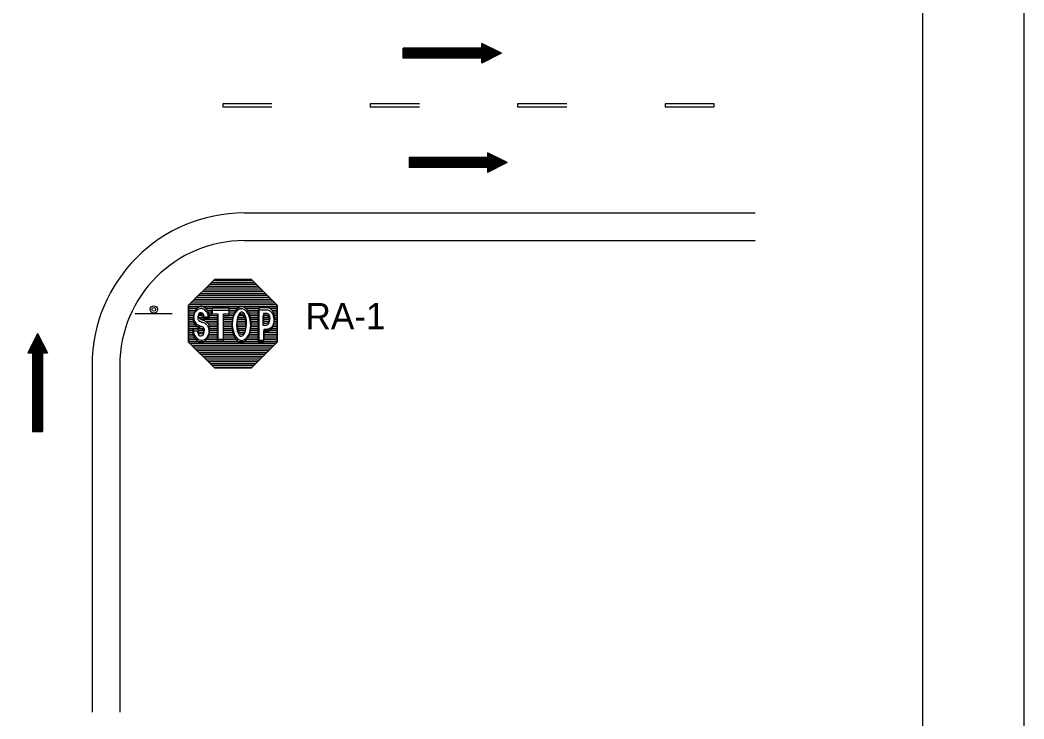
# Model space of a CAD drawing. Extents: x 2111 to 2327, y 208 to 487.
# Drawn here: x 2228.5 to 2327.3, y 280.7 to 349.6 of the extents above; entities that cross this region are included whole.
import ezdxf

# ---------------------------------------------------------------- set-up
doc = ezdxf.new("R2010")
doc.units = 0
for name, color, linetype in [('Level 10', 7, 'Continuous'), ('Level 2', 7, 'Continuous'), ('Level 44', 7, 'Continuous'), ('Level 60', 7, 'Continuous')]:
    doc.layers.add(name, color=color, linetype=linetype)

msp = doc.modelspace()

# ---------------------------------------------------------------- linework, layer by layer
at = {"layer": 'Level 10'}
for p, q in [((2275.874, 346.307), (2273.937, 347.276)), ((2273.937, 346.791), (2273.937, 347.276)), ((2274.181, 347.153), (2273.937, 347.153)), ((2274.422, 347.032), (2273.937, 347.032)), ((2273.937, 346.791), (2266.196, 346.791)), ((2266.196, 345.824), (2266.196, 346.791)), ((2274.906, 346.791), (2266.196, 346.791)), ((2275.148, 346.67), (2266.196, 346.67)), ((2275.389, 346.549), (2266.196, 346.549)), ((2275.631, 346.428), (2266.196, 346.428)), ((2275.874, 346.307), (2266.196, 346.307)), ((2275.631, 346.186), (2266.196, 346.186)), ((2275.389, 346.065), (2266.196, 346.065)), ((2274.664, 346.913), (2273.937, 346.913)), ((2275.874, 346.307), (2273.937, 345.338)), ((2275.148, 345.944), (2266.196, 345.944)), ((2273.937, 345.824), (2266.196, 345.824)), ((2274.906, 345.824), (2266.196, 345.824)), ((2273.937, 345.338), (2273.937, 345.824)), ((2274.664, 345.703), (2273.937, 345.703)), ((2274.422, 345.582), (2273.937, 345.582)), ((2274.181, 345.461), (2273.937, 345.461)), ((2276.452, 335.537), (2274.516, 336.504)), ((2274.516, 336.504), (2274.516, 336.021)), ((2274.758, 336.384), (2274.516, 336.384)), ((2275, 336.263), (2274.516, 336.263)), ((2275.242, 336.142), (2274.516, 336.142)), ((2274.516, 336.021), (2266.774, 336.021)), ((2266.774, 336.021), (2266.774, 335.052)), ((2275.484, 336.021), (2266.774, 336.021)), ((2275.725, 335.9), (2266.774, 335.9)), ((2275.967, 335.779), (2266.774, 335.779)), ((2276.209, 335.658), (2266.774, 335.658)), ((2276.452, 335.537), (2266.774, 335.537)), ((2276.209, 335.416), (2266.774, 335.416)), ((2275.967, 335.296), (2266.774, 335.296)), ((2275.725, 335.173), (2266.774, 335.173)), ((2276.452, 335.537), (2274.516, 334.569)), ((2274.516, 335.052), (2266.774, 335.052)), ((2275.484, 335.052), (2266.774, 335.052)), ((2274.516, 335.052), (2274.516, 334.569)), ((2275.242, 334.933), (2274.516, 334.933)), ((2275, 334.81), (2274.516, 334.81)), ((2274.758, 334.69), (2274.516, 334.69)), ((2250.564, 330.571), (2300.839, 330.571)), ((2250.564, 327.844), (2300.839, 327.844)), ((2230.192, 318.708), (2229.225, 316.772)), ((2230.071, 318.465), (2230.071, 309.03)), ((2230.192, 318.708), (2230.192, 309.03)), ((2230.192, 318.708), (2231.16, 316.772)), ((2230.313, 318.465), (2230.313, 309.03)), ((2229.587, 317.498), (2229.587, 316.772)), ((2229.708, 317.74), (2229.708, 309.03)), ((2229.829, 317.981), (2229.829, 309.03)), ((2229.95, 318.223), (2229.95, 309.03)), ((2230.433, 318.223), (2230.433, 309.03)), ((2230.556, 317.981), (2230.556, 309.03)), ((2230.677, 317.74), (2230.677, 309.03)), ((2230.796, 317.498), (2230.796, 316.772)), ((2229.225, 316.772), (2229.708, 316.772)), ((2229.345, 317.014), (2229.345, 316.772)), ((2229.466, 317.256), (2229.466, 316.772)), ((2229.708, 316.772), (2229.708, 309.03)), ((2230.677, 316.772), (2230.677, 309.03)), ((2230.677, 316.772), (2231.16, 316.772)), ((2230.919, 317.256), (2230.919, 316.772)), ((2231.039, 317.014), (2231.039, 316.772)), ((2235.564, 315.571), (2235.564, 281.396)), ((2238.291, 315.571), (2238.291, 281.396)), ((2229.708, 309.03), (2230.677, 309.03))]:
    msp.add_line(p, q, dxfattribs=at)
for radius in [15, 12.273]:
    msp.add_arc((2250.564, 315.571), radius, 90, 180, dxfattribs=at)
at = {"layer": 'Level 2'}
for p, q in [((2253.279, 341.303), (2248.441, 341.303)), ((2248.441, 341.303), (2248.441, 341.013)), ((2248.441, 341.013), (2253.279, 341.013)), ((2267.793, 341.303), (2262.955, 341.303)), ((2262.955, 341.303), (2262.955, 341.013)), ((2262.955, 341.013), (2267.793, 341.013)), ((2282.307, 341.303), (2277.469, 341.303)), ((2277.469, 341.303), (2277.469, 341.013)), ((2277.469, 341.013), (2282.307, 341.013)), ((2296.821, 341.303), (2291.983, 341.303)), ((2291.983, 341.303), (2291.983, 341.013)), ((2291.983, 341.013), (2296.821, 341.013)), ((2296.821, 341.013), (2296.821, 341.303))]:
    msp.add_line(p, q, dxfattribs=at)
at = {"layer": 'Level 44'}
for p, q in [((2247.623, 324.02), (2245.075, 321.474)), ((2251.252, 324.02), (2247.623, 324.02)), ((2253.8, 321.474), (2251.252, 324.02)), ((2245.075, 321.474), (2245.075, 317.844)), ((2253.8, 317.844), (2253.8, 321.474)), ((2239.822, 320.657), (2243.451, 320.657)), ((2247.114, 320.305), (2246.57, 320.305)), ((2247.33, 320.428), (2247.33, 320.987)), ((2247.33, 320.987), (2249.031, 320.987)), ((2247.919, 320.428), (2247.33, 320.428)), ((2247.377, 321.198), (2247.377, 320.639)), ((2249.074, 321.198), (2247.377, 321.198)), ((2247.377, 320.639), (2247.963, 320.639)), ((2247.919, 317.916), (2247.919, 320.428)), ((2247.963, 320.639), (2247.963, 318.126)), ((2249.031, 320.414), (2248.471, 320.414)), ((2248.471, 320.414), (2248.471, 317.916)), ((2248.516, 318.126), (2248.516, 320.624)), ((2248.516, 320.624), (2249.074, 320.624)), ((2249.031, 320.987), (2249.031, 320.414)), ((2249.074, 320.624), (2249.074, 321.198)), ((2250.206, 320.584), (2250.229, 320.589)), ((2250.228, 321.128), (2250.244, 321.129)), ((2251.926, 317.823), (2251.926, 321.015)), ((2251.926, 321.015), (2252.82, 321.015)), ((2252.863, 321.227), (2251.971, 321.227)), ((2251.971, 321.227), (2251.971, 318.033)), ((2252.391, 320.443), (2252.391, 319.514)), ((2252.738, 320.443), (2252.391, 320.443)), ((2252.738, 320.443), (2252.391, 320.443)), ((2252.391, 320.443), (2252.391, 319.514)), ((2252.783, 320.653), (2252.435, 320.653)), ((2252.435, 320.653), (2252.435, 319.724)), ((2252.435, 320.653), (2252.435, 319.724)), ((2252.783, 320.653), (2252.435, 320.653)), ((2247.07, 320.094), (2246.525, 320.094)), ((2252.391, 319.514), (2252.731, 319.514)), ((2252.391, 319.514), (2252.731, 319.514)), ((2252.435, 319.724), (2252.777, 319.724)), ((2252.435, 319.724), (2252.777, 319.724)), ((2245.452, 318.948), (2245.952, 318.948)), ((2245.495, 319.158), (2245.998, 319.158)), ((2245.61, 318.315), (2245.608, 318.318)), ((2252.773, 318.919), (2252.456, 318.91)), ((2252.456, 318.91), (2252.79, 318.91)), ((2252.456, 318.91), (2252.456, 317.823)), ((2252.501, 318.033), (2252.501, 319.121)), ((2252.501, 319.121), (2252.835, 319.121)), ((2245.075, 317.844), (2247.623, 315.296)), ((2248.471, 317.916), (2247.919, 317.916)), ((2247.963, 318.126), (2248.516, 318.126)), ((2251.252, 315.296), (2253.8, 317.844)), ((2252.456, 317.823), (2251.926, 317.823)), ((2251.971, 318.033), (2252.501, 318.033)), ((2247.623, 315.296), (2251.252, 315.296))]:
    msp.add_line(p, q, dxfattribs=at)
msp.add_lwpolyline([(2253.801, 317.844), (2251.252, 315.296), (2247.623, 315.296), (2245.075, 317.844), (2245.075, 321.474), (2247.623, 324.022), (2251.252, 324.022), (2253.801, 321.474)], close=True, dxfattribs=at)
for points in [[(2246.963, 323.359), (2251.913, 323.359)], [(2247.143, 323.542), (2251.732, 323.542)], [(2247.325, 323.724), (2251.543, 323.724)], [(2247.508, 323.904), (2251.368, 323.904)], [(2245.873, 322.272), (2253.002, 322.272)], [(2246.055, 322.453), (2252.82, 322.453)], [(2246.237, 322.634), (2252.638, 322.634)], [(2246.418, 322.817), (2252.457, 322.817)], [(2246.599, 322.998), (2252.275, 322.998)], [(2246.78, 323.179), (2252.087, 323.179)], [(2245.075, 321.364), (2253.8, 321.364)], [(2245.148, 321.545), (2253.727, 321.545)], [(2245.328, 321.728), (2253.546, 321.728)], [(2245.51, 321.909), (2253.365, 321.909)], [(2245.693, 322.089), (2253.183, 322.089)], [(2245.075, 321.183), (2245.917, 321.183)], [(2245.075, 321.002), (2245.764, 321.002)], [(2245.075, 320.819), (2245.663, 320.819)], [(2245.075, 320.639), (2245.613, 320.639)], [(2245.075, 320.458), (2245.577, 320.458)], [(2245.075, 320.275), (2245.568, 320.275)], [(2246.012, 320.458), (2246.578, 320.458)], [(2246.04, 320.275), (2247.963, 320.275)], [(2246.092, 320.639), (2246.498, 320.639)], [(2246.753, 321.183), (2247.377, 321.183)], [(2246.912, 321.002), (2247.377, 321.002)], [(2247.013, 320.819), (2247.377, 320.819)], [(2247.064, 320.639), (2247.377, 320.639)], [(2247.108, 320.458), (2247.963, 320.458)], [(2248.516, 320.458), (2249.482, 320.458)], [(2248.516, 320.275), (2249.437, 320.275)], [(2249.074, 321.183), (2249.917, 321.183)], [(2249.074, 321.002), (2249.749, 321.002)], [(2249.074, 320.819), (2249.627, 320.819)], [(2249.074, 320.639), (2249.546, 320.639)], [(2249.903, 320.275), (2250.693, 320.275)], [(2249.953, 320.458), (2250.634, 320.458)], [(2250.039, 320.639), (2250.548, 320.639)], [(2250.686, 321.183), (2251.971, 321.183)], [(2250.861, 321.002), (2251.971, 321.002)], [(2250.977, 320.819), (2251.971, 320.819)], [(2251.056, 320.639), (2251.971, 320.639)], [(2251.122, 320.458), (2251.971, 320.458)], [(2251.164, 320.275), (2251.971, 320.275)], [(2252.435, 320.639), (2252.856, 320.639)], [(2252.435, 320.458), (2253.03, 320.458)], [(2252.435, 320.275), (2253.073, 320.275)], [(2253.03, 321.183), (2253.8, 321.183)], [(2253.263, 321.002), (2253.8, 321.002)], [(2253.378, 320.819), (2253.8, 320.819)], [(2253.466, 320.639), (2253.8, 320.639)], [(2253.508, 320.458), (2253.8, 320.458)], [(2253.532, 320.275), (2253.8, 320.275)], [(2245.075, 320.094), (2245.592, 320.094)], [(2245.075, 319.913), (2245.642, 319.913)], [(2245.075, 319.73), (2245.758, 319.73)], [(2245.075, 319.55), (2245.989, 319.55)], [(2245.075, 319.369), (2246.418, 319.369)], [(2246.273, 320.094), (2247.963, 320.094)], [(2246.679, 319.913), (2247.963, 319.913)], [(2246.927, 319.73), (2247.963, 319.73)], [(2247.064, 319.55), (2247.963, 319.55)], [(2247.114, 319.369), (2247.963, 319.369)], [(2248.516, 320.094), (2249.408, 320.094)], [(2248.516, 319.73), (2249.379, 319.73)], [(2248.516, 319.55), (2249.379, 319.55)], [(2248.516, 319.369), (2249.393, 319.369)], [(2248.523, 319.913), (2249.387, 319.913)], [(2249.829, 319.73), (2250.767, 319.73)], [(2249.829, 319.55), (2250.773, 319.55)], [(2249.843, 319.913), (2250.767, 319.913)], [(2249.852, 320.094), (2250.737, 320.094)], [(2249.852, 319.369), (2250.752, 319.369)], [(2251.201, 320.094), (2251.971, 320.094)], [(2251.208, 319.369), (2251.971, 319.369)], [(2251.216, 319.913), (2251.971, 319.913)], [(2251.223, 319.55), (2251.971, 319.55)], [(2251.231, 319.73), (2251.971, 319.73)], [(2252.428, 320.094), (2253.081, 320.094)], [(2252.435, 319.913), (2253.023, 319.913)], [(2253.278, 319.369), (2253.8, 319.369)], [(2253.401, 319.55), (2253.8, 319.55)], [(2253.466, 319.73), (2253.8, 319.73)], [(2253.517, 319.913), (2253.8, 319.913)], [(2253.538, 320.094), (2253.8, 320.094)], [(2245.075, 319.188), (2246.607, 319.188)], [(2245.075, 319.005), (2245.518, 319.005)], [(2245.075, 318.824), (2245.554, 318.824)], [(2245.075, 318.643), (2245.613, 318.643)], [(2245.075, 318.46), (2245.698, 318.46)], [(2245.075, 318.28), (2245.844, 318.28)], [(2246.012, 319.005), (2246.628, 319.005)], [(2246.07, 318.824), (2246.585, 318.824)], [(2246.853, 318.28), (2247.963, 318.28)], [(2246.983, 318.46), (2247.963, 318.46)], [(2247.072, 318.643), (2247.963, 318.643)], [(2247.129, 318.824), (2247.963, 318.824)], [(2247.143, 319.188), (2247.963, 319.188)], [(2247.143, 319.005), (2247.963, 319.005)], [(2248.516, 319.188), (2249.416, 319.188)], [(2248.516, 319.005), (2249.444, 319.005)], [(2248.516, 318.824), (2249.496, 318.824)], [(2248.516, 318.643), (2249.561, 318.643)], [(2248.516, 318.46), (2249.654, 318.46)], [(2248.516, 318.28), (2249.786, 318.28)], [(2249.888, 319.188), (2250.716, 319.188)], [(2249.946, 319.005), (2250.664, 319.005)], [(2250.024, 318.824), (2250.569, 318.824)], [(2250.794, 318.28), (2251.971, 318.28)], [(2250.926, 318.46), (2251.971, 318.46)], [(2251.019, 318.643), (2251.971, 318.643)], [(2251.092, 318.824), (2251.971, 318.824)], [(2251.143, 319.005), (2251.971, 319.005)], [(2251.179, 319.188), (2251.971, 319.188)], [(2252.501, 319.005), (2253.8, 319.005)], [(2252.501, 318.824), (2253.8, 318.824)], [(2252.501, 318.643), (2253.8, 318.643)], [(2252.501, 318.46), (2253.8, 318.46)], [(2252.501, 318.28), (2253.8, 318.28)], [(2253.03, 319.188), (2253.8, 319.188)], [(2245.075, 318.099), (2246.055, 318.099)], [(2245.075, 317.916), (2253.8, 317.916)], [(2245.184, 317.735), (2253.691, 317.735)], [(2245.365, 317.554), (2253.508, 317.554)], [(2245.547, 317.373), (2253.328, 317.373)], [(2246.613, 318.099), (2250.003, 318.099)], [(2250.577, 318.099), (2251.971, 318.099)], [(2252.501, 318.099), (2253.8, 318.099)], [(2245.728, 317.19), (2253.147, 317.19)], [(2245.91, 317.009), (2252.965, 317.009)], [(2246.092, 316.829), (2252.783, 316.829)], [(2246.273, 316.646), (2252.602, 316.646)], [(2246.453, 316.465), (2252.421, 316.465)], [(2246.635, 316.284), (2252.238, 316.284)], [(2246.818, 316.101), (2252.058, 316.101)], [(2246.998, 315.921), (2251.877, 315.921)], [(2247.18, 315.739), (2251.695, 315.739)], [(2247.368, 315.559), (2251.513, 315.559)], [(2247.543, 315.376), (2251.332, 315.376)]]:
    msp.add_lwpolyline(points, dxfattribs=at)
for radius in [0.363, 0.181]:
    msp.add_circle((2241.644, 321.064), radius, dxfattribs=at)
for centre, radius, start, end in [((2246.553, 320.459), 0.967, 123.3662, 155.67344), ((2246.331, 320.762), 0.591, 46.13686, 121.39871), ((2246.88, 320.131), 1.355, 157.73321, 177.13918), ((2246.757, 320.304), 1.19, 174.81715, 195.91834), ((2246.925, 320.342), 1.355, 157.73321, 177.13918), ((2246.509, 320.248), 0.967, 123.3662, 155.67344), ((2246.224, 320.197), 0.268, 164.13099, 238.14757), ((2246.259, 320.239), 0.294, 113.8064, 172.24074), ((2246.287, 320.552), 0.591, 46.13686, 121.39871), ((2246.269, 320.407), 0.268, 164.13099, 238.14757), ((2246.304, 320.45), 0.294, 113.8064, 172.24074), ((2246.236, 320.215), 0.308, 47.30173, 109.01194), ((2246.28, 320.426), 0.308, 47.30173, 109.01194), ((2246.092, 320.161), 0.45, 350.44122, 39.32441), ((2246.136, 320.372), 0.45, 350.44122, 39.32441), ((2246.04, 320.227), 0.998, 14.56402, 49.00631), ((2246.085, 320.438), 0.998, 14.56402, 49.00631), ((2245.686, 320.07), 1.381, 0.69518, 17.14515), ((2245.731, 320.281), 1.381, 0.69518, 17.14515), ((2252.685, 320.141), 0.315, 35.11978, 79.31166), ((2252.685, 320.141), 0.315, 35.11978, 79.31166), ((2252.73, 320.352), 0.315, 35.11978, 79.31166), ((2252.73, 320.352), 0.315, 35.11978, 79.31166), ((2252.771, 320.491), 0.53, 44.85284, 85.0441), ((2252.816, 320.701), 0.53, 44.85284, 85.0441), ((2252.538, 320.047), 0.489, 8.60306, 34.21696), ((2252.538, 320.047), 0.489, 8.60306, 34.21696), ((2252.583, 320.258), 0.489, 8.60306, 34.21696), ((2252.583, 320.258), 0.489, 8.60306, 34.21696), ((2252.565, 320.194), 0.52, 350.34165, 15.23421), ((2252.565, 320.194), 0.52, 350.34165, 15.23421), ((2252.605, 320.258), 0.814, 29.22414, 48.53082), ((2252.605, 320.258), 0.814, 29.22414, 48.53082), ((2252.65, 320.468), 0.814, 29.22414, 48.53082), ((2252.65, 320.468), 0.814, 29.22414, 48.53082), ((2252.594, 320.179), 0.864, 13.06738, 33.76202), ((2252.639, 320.389), 0.864, 13.06738, 33.76202), ((2251.818, 319.923), 1.68, 3.39027, 15.65974), ((2251.863, 320.134), 1.68, 3.39027, 15.65974), ((2246.713, 320.093), 1.19, 174.81715, 195.91834), ((2246.363, 320.058), 0.847, 200.4481, 235.11069), ((2246.408, 320.269), 0.847, 200.4481, 235.11069), ((2248.532, 324.894), 6.135, 244.46241, 248.83121), ((2248.577, 325.105), 6.135, 244.46241, 248.83121), ((2247.072, 321.551), 1.866, 237.98164, 250.97904), ((2247.117, 321.762), 1.866, 237.98164, 250.97904), ((2246.261, 319.01), 0.387, 34.20826, 74.15525), ((2245.976, 318.576), 1.305, 46.24648, 67.92633), ((2246.021, 318.786), 1.305, 46.24648, 67.92633), ((2248.645, 320.964), 2.281, 219.47897, 223.42605), ((2248.689, 321.174), 2.281, 219.47897, 223.42605), ((2245.74, 318.868), 1.359, 5.90969, 21.9865), ((2245.785, 319.078), 1.359, 5.90969, 21.9865), ((2252.658, 319.867), 0.361, 281.91914, 325.7868), ((2252.658, 319.867), 0.361, 281.91914, 325.7868), ((2252.703, 320.078), 0.361, 281.91914, 325.7868), ((2252.703, 320.078), 0.361, 281.91914, 325.7868), ((2252.569, 319.92), 0.464, 326.50855, 357.0313), ((2252.569, 319.92), 0.464, 326.50855, 357.0313), ((2252.614, 320.131), 0.464, 326.50855, 357.0313), ((2252.614, 320.131), 0.464, 326.50855, 357.0313), ((2252.52, 319.983), 0.52, 350.34165, 15.23421), ((2252.52, 319.983), 0.52, 350.34165, 15.23421), ((2252.851, 319.688), 0.531, 295.38384, 322.61875), ((2252.583, 319.724), 0.86, 318.29225, 338.60313), ((2252.583, 319.724), 0.86, 318.29225, 338.60313), ((2252.628, 319.935), 0.86, 318.29225, 338.60313), ((2252.628, 319.935), 0.86, 318.29225, 338.60313), ((2251.745, 320.061), 1.764, 338.31533, 348.66985), ((2251.79, 320.272), 1.764, 338.31533, 348.66985), ((2252.147, 319.956), 1.35, 349.75207, 2.79164), ((2252.147, 319.956), 1.35, 349.75207, 2.79164), ((2252.191, 320.167), 1.35, 349.75207, 2.79164), ((2252.191, 320.167), 1.35, 349.75207, 2.79164), ((2247.121, 319.021), 1.669, 182.38409, 204.95188), ((2247.166, 319.232), 1.669, 182.38409, 204.95188), ((2246.657, 318.881), 1.189, 208.41538, 233.65531), ((2246.702, 319.092), 1.189, 208.41538, 233.65531), ((2246.708, 318.939), 0.761, 179.01715, 193.51721), ((2246.35, 318.796), 0.382, 186.87276, 222.74491), ((2246.753, 319.15), 0.761, 179.01715, 193.51721), ((2246.394, 319.006), 0.382, 186.87276, 222.74491), ((2246.298, 318.83), 0.372, 230.6966, 271.45727), ((2246.343, 319.041), 0.372, 230.6966, 271.45727), ((2246.271, 318.801), 0.345, 275.4374, 314.06255), ((2246.216, 318.799), 0.387, 34.20826, 74.15525), ((2246.316, 319.012), 0.345, 275.4374, 314.06255), ((2246.121, 318.798), 0.459, 326.25303, 358.73226), ((2246.228, 318.84), 0.355, 352.57609, 30.47756), ((2246.204, 318.858), 0.868, 293.14132, 324.99056), ((2246.166, 319.009), 0.459, 326.25303, 358.73226), ((2246.273, 319.051), 0.355, 352.57609, 30.47756), ((2245.624, 319.005), 1.513, 325.50918, 343.2894), ((2245.669, 319.216), 1.513, 325.50918, 343.2894), ((2245.173, 318.872), 1.924, 351.24702, 3.9864), ((2245.218, 319.082), 1.924, 351.24702, 3.9864), ((2252.806, 319.1), 0.184, 259.79086, 293.54187), ((2252.851, 319.311), 0.184, 259.79086, 293.54187), ((2252.649, 319.68), 0.784, 286.60198, 299.80906), ((2252.693, 319.891), 0.784, 286.60198, 299.80906), ((2252.807, 319.477), 0.531, 295.38384, 322.61875), ((2246.287, 318.352), 0.544, 232.05359, 292.73967), ((2246.331, 318.563), 0.544, 232.05359, 292.73967), ((2246.159, 318.647), 0.868, 293.14132, 324.99056)]:
    msp.add_arc(centre, radius, start, end, dxfattribs=at)
for centre, major_axis, ratio, start_param, end_param in [((2250.302, 319.676), (-0.011, -1.663), 0.558644, 3.185857, 9.451311), ((2250.257, 319.466), (-0.011, -1.663), 0.558644, 4.129576, 6.939747), ((2250.257, 319.466), (-0.011, -1.663), 0.558644, 3.185857, 4.129398), ((2250.257, 319.504), (0.006, -1.086), 0.432619, 3.890436, 7.165085), ((2250.302, 319.715), (0.006, -1.086), 0.432619, 3.239639, 9.473919), ((2250.257, 319.504), (0.006, -1.086), 0.432619, 3.239639, 3.888884), ((2250.257, 319.504), (0.006, -1.086), 0.432619, 0.881967, 3.190734), ((2250.257, 319.466), (-0.011, -1.663), 0.558644, 0.656861, 3.168126)]:
    msp.add_ellipse(centre, major_axis=major_axis, ratio=ratio, start_param=start_param, end_param=end_param, dxfattribs=at)
at = {"layer": 'Level 60'}
for points in [[(2111.318, 487.207), (2327.318, 487.207), (2327.318, 208.207), (2111.318, 208.207)], [(2130.444, 476.398), (2317.318, 476.398), (2317.318, 219.016), (2130.444, 219.016)]]:
    msp.add_lwpolyline(points, close=True, dxfattribs=at)

# ---------------------------------------------------------------- texts
at = {"layer": 'Level 10'}
msp.add_text('RA-1', height=2.5853, dxfattribs=at).set_placement((2256.58, 319.113))

doc.saveas('drawing.dxf')
